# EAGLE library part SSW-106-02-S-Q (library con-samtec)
THROUGH-HOLE .025" SQ POST SOCKET Source: Samtec SSW.pdf
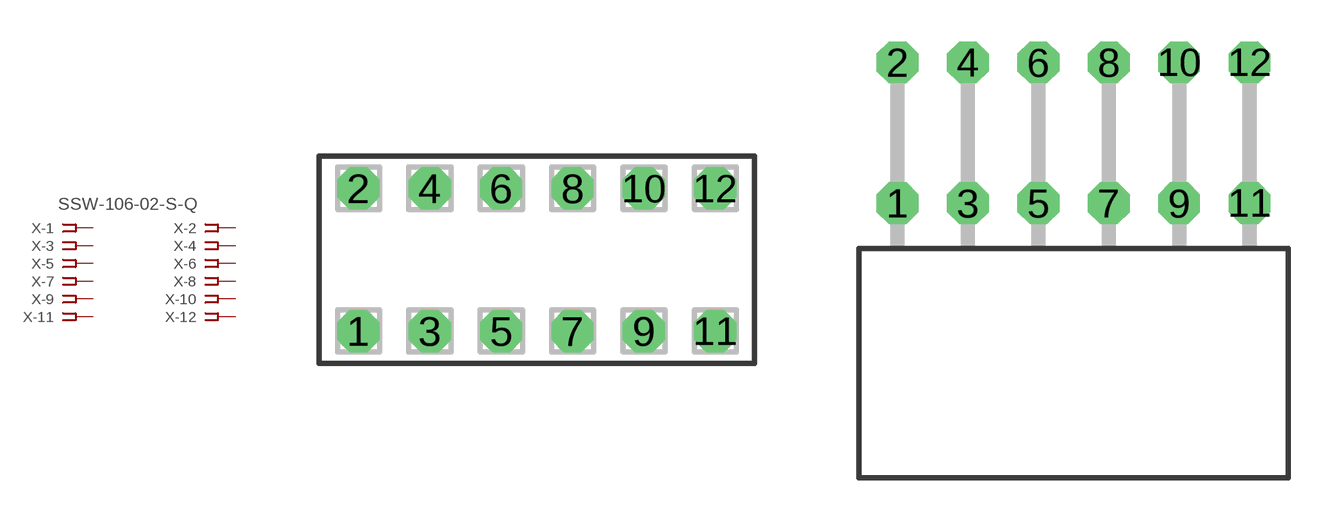
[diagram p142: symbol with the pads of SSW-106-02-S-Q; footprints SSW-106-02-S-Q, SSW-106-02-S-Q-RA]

Designator prefix X; gates -1=FPINV -2=FPIN -3=FPIN -4=FPIN -5=FPIN -6=FPIN -7=FPIN -8=FPIN -9=FPIN -10=FPIN -11=FPIN -12=FPIN

## SSW-106-02-S-Q (MPN: SSW-106-02-S-Q; OC_FARNELL: unknown; OC_NEWARK: 82P3410)  [SSW-106-02-S-Q]
1  -1:1  pas
2  -2:1  pas
3  -3:1  pas
4  -4:1  pas
5  -5:1  pas
6  -6:1  pas
7  -7:1  pas
8  -8:1  pas
9  -9:1  pas
10  -10:1  pas
11  -11:1  pas
12  -12:1  pas

## SSW-106-02-S-QRA (MPN: SSW-106-02-S-Q-RA; OC_FARNELL: unknown; OC_NEWARK: 82P3411)  [SSW-106-02-S-Q-RA]
Pads as for SSW-106-02-S-Q

## Footprint SSW-106-02-S-Q (pad centres in mm)
THROUGH-HOLE .025" SQ POST SOCKET Source: Samtec SSW.pdf
drill 1 pad 1.5 octagon: 1 -6.35,-2.54; 2 -6.35,2.54; 3 -3.81,-2.54; 4 -3.81,2.54; 5 -1.27,-2.54; 6 -1.27,2.54; 7 1.27,-2.54; 8 1.27,2.54; 9 3.81,-2.54; 10 3.81,2.54; 11 6.35,-2.54; 12 6.35,2.54

## Footprint SSW-106-02-S-Q-RA (pad centres in mm)
THROUGH-HOLE .025" SQ POST SOCKET Source: Samtec SSW.pdf
drill 1 pad 1.5 octagon: 1 -6.35,1.524; 2 -6.35,6.604; 3 -3.81,1.524; 4 -3.81,6.604; 5 -1.27,1.524; 6 -1.27,6.604; 7 1.27,1.524; 8 1.27,6.604; 9 3.81,1.524; 10 3.81,6.604; 11 6.35,1.524; 12 6.35,6.604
